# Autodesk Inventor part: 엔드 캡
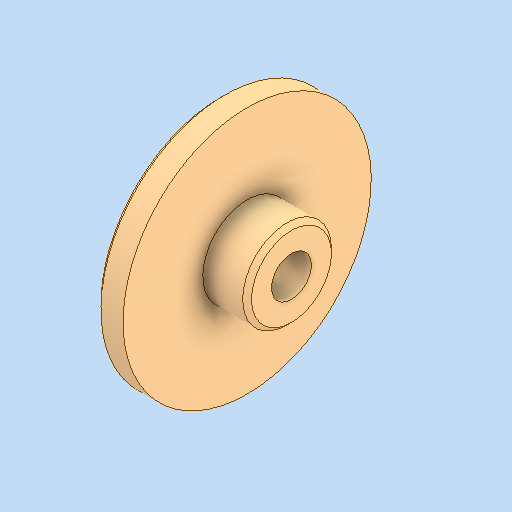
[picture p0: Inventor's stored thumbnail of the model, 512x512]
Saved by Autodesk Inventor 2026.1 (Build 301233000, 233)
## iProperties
Created: 2025-11
Part Number: 엔드 캡
Material: 강철, 연강
Document SubType Name: Modeling
Designer: PC-30
Density: 7.85 g/cm^3
Appearance: 기본값
Author: jhkim
Sending System: Autodesk Inventor 2026
Preprocessor: ST-DEVELOPER v20.1
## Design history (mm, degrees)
feature "솔리드1"
node "솔리드2"
